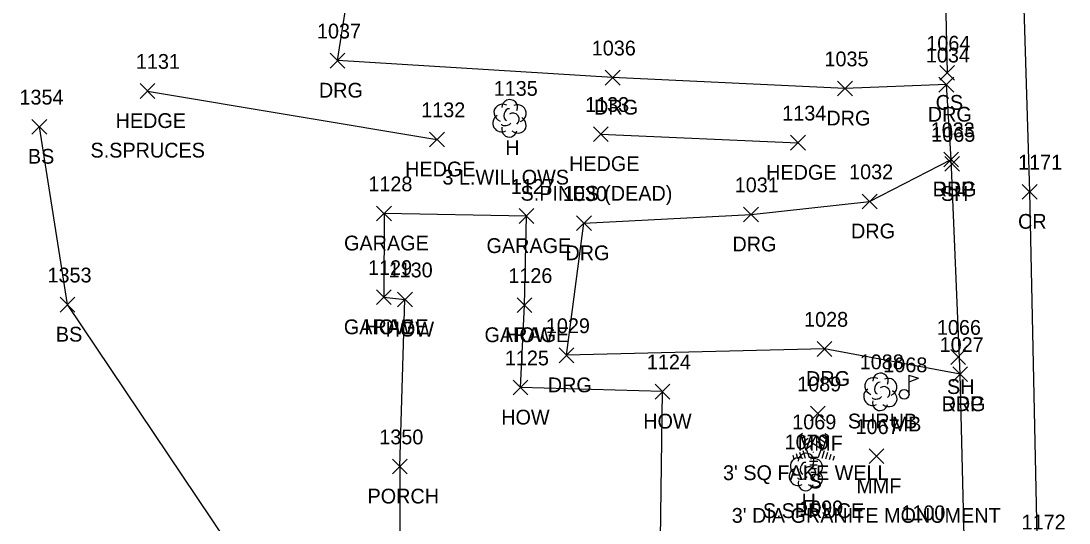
# Model space of a CAD drawing. Extents: x 1609623 to 1616187, y 756677 to 762826.
# Drawn here: x 1610487.5 to 1610629.1, y 761449.2 to 761517.1 of the extents above; entities that cross this region are included whole.
import ezdxf

# ---------------------------------------------------------------- set-up
doc = ezdxf.new("R2010")
doc.units = 0
for name, color, linetype in [('L_A', 7, 'Continuous'), ('L_C', 7, 'Continuous'), ('L_I', 7, 'Continuous'), ('L_TIC', 7, 'Continuous'), ('LAHR', 7, 'Continuous'), ('LBC', 7, 'Continuous'), ('LBF', 7, 'Continuous'), ('LELB', 7, 'Continuous'), ('LMB', 7, 'Continuous'), ('LSH', 7, 'Continuous'), ('LTC', 7, 'Continuous'), ('LTD', 7, 'Continuous'), ('P_A', 7, 'Continuous'), ('P_I', 7, 'Continuous'), ('P_TIC', 7, 'Continuous'), ('PET', 7, 'Continuous'), ('PRC', 7, 'Continuous'), ('R_A', 7, 'Continuous'), ('R_I', 7, 'Continuous'), ('R_TIC', 7, 'Continuous'), ('RDG', 7, 'Continuous')]:
    doc.layers.add(name, color=color, linetype=linetype)

msp = doc.modelspace()

# ---------------------------------------------------------------- linework, layer by layer
at = {"layer": 'L_TIC'}
for points in [[(1610611.63, 761509.1), (1610613.63, 761511.1)], [(1610613.63, 761509.1), (1610611.63, 761511.1)], [(1610503.6, 761506.64), (1610505.6, 761508.64)], [(1610505.6, 761506.64), (1610503.6, 761508.64)], [(1610489, 761501.81), (1610491, 761503.81)], [(1610491, 761501.81), (1610489, 761503.81)], [(1610564.85, 761500.81), (1610566.85, 761502.81)], [(1610566.85, 761500.81), (1610564.85, 761502.81)], [(1610542.71, 761500.09), (1610544.71, 761502.09)], [(1610544.71, 761500.09), (1610542.71, 761502.09)], [(1610591.47, 761499.65), (1610593.47, 761501.65)], [(1610593.47, 761499.65), (1610591.47, 761501.65)], [(1610612.3, 761496.78), (1610614.3, 761498.78)], [(1610614.3, 761496.78), (1610612.3, 761498.78)], [(1610535.56, 761490.08), (1610537.56, 761492.08)], [(1610537.56, 761490.08), (1610535.56, 761492.08)], [(1610554.81, 761489.73), (1610556.81, 761491.73)], [(1610556.81, 761489.73), (1610554.81, 761491.73)], [(1610492.79, 761477.75), (1610494.79, 761479.75)], [(1610494.79, 761477.75), (1610492.79, 761479.75)], [(1610535.53, 761478.75), (1610537.53, 761480.75)], [(1610537.53, 761478.75), (1610535.53, 761480.75)], [(1610535.53, 761478.75), (1610537.53, 761480.75)], [(1610537.53, 761478.75), (1610535.53, 761480.75)], [(1610538.39, 761478.44), (1610540.39, 761480.44)], [(1610540.39, 761478.44), (1610538.39, 761480.44)], [(1610554.53, 761477.68), (1610556.53, 761479.68)], [(1610556.53, 761477.68), (1610554.53, 761479.68)], [(1610554.53, 761477.68), (1610556.53, 761479.68)], [(1610556.53, 761477.68), (1610554.53, 761479.68)], [(1610613.11, 761470.67), (1610615.11, 761472.67)], [(1610615.11, 761470.67), (1610613.11, 761472.67)], [(1610554, 761466.54), (1610556, 761468.54)], [(1610556, 761466.54), (1610554, 761468.54)], [(1610573.18, 761465.99), (1610575.18, 761467.99)], [(1610575.18, 761465.99), (1610573.18, 761467.99)], [(1610594.15, 761463.02), (1610596.15, 761465.02)], [(1610596.15, 761463.02), (1610594.15, 761465.02)], [(1610602.07, 761457.25), (1610604.07, 761459.25)], [(1610604.07, 761457.25), (1610602.07, 761459.25)], [(1610537.7, 761455.86), (1610539.7, 761457.86)], [(1610539.7, 761455.86), (1610537.7, 761457.86)]]:
    msp.add_lwpolyline(points, dxfattribs=at)
at = {"layer": 'LAHR'}
for points in [[(1610504.6, 761507.64), (1610543.71, 761501.09)], [(1610565.85, 761501.81), (1610592.47, 761500.65)]]:
    msp.add_lwpolyline(points, dxfattribs=at)
at = {"layer": 'LBC'}
for points in [[(1610555.53, 761478.68), (1610555.81, 761490.73), (1610536.56, 761491.08), (1610536.53, 761479.75)], [(1610536.53, 761479.75), (1610539.39, 761479.44)], [(1610544.98, 761440.64), (1610573.82, 761440.42), (1610574.18, 761466.99), (1610555, 761467.54), (1610555.53, 761478.68)]]:
    msp.add_lwpolyline(points, dxfattribs=at)
at = {"layer": 'LBF'}
for points in [[(1610538.7, 761456.86), (1610539.39, 761479.44)], [(1610538.7, 761456.86), (1610538.69, 761440.44)]]:
    msp.add_lwpolyline(points, dxfattribs=at)
at = {"layer": 'LELB'}
for points in [[(1610611.15, 761569.53), (1610611.94, 761540.19), (1610612.63, 761510.1)], [(1610528.82, 761426.55), (1610493.79, 761478.75), (1610490, 761502.81)]]:
    msp.add_lwpolyline(points, dxfattribs=at)
at = {"layer": 'LMB'}
for p, q in [((1610607.47, 761469.21), (1610608.77, 761468.83)), ((1610607.48, 761466.62), (1610607.48, 761469.21)), ((1610607.48, 761468.31), (1610608.76, 761468.82)), ((1610606.82, 761466.61), (1610606.82, 761466.61))]:
    msp.add_line(p, q, dxfattribs=at)
msp.add_circle((1610606.82, 761466.61), 0.656, dxfattribs=at)
at = {"layer": 'LSH'}
msp.add_line((1610603.58, 761467.01), (1610603.58, 761467.01), dxfattribs=at)
msp.add_line((1610603.58, 761467.01), (1610603.58, 761467.01), dxfattribs=at)
msp.add_arc((1610603.63, 761468.44), 1.05, 335.5272, 180.9563, dxfattribs=at)
for centre, major_axis, ratio, start_param, end_param in [((1610602.79, 761467.67), (1.21, -0.51), 0.895232, 1.570796, 4.712389), ((1610603.37, 761467.46), (-0.208, -0.792), 0.645439, 3.141593, 6.283185), ((1610604.62, 761467.59), (-1.14, -0.48), 0.949671, 1.570796, 4.712389), ((1610602.5, 761466.3), (0.58, -1.04), 0.959034, 3.141593, 6.283185), ((1610604.08, 761466.84), (-0.5, 0.667), 0.989748, 3.141593, 6.283185), ((1610604.58, 761466.17), (-1.09, 0.79), 0.841452, 1.570796, 4.712389), ((1610603.58, 761465.51), (0.26, 1.06), 0.942809, 1.570796, 4.712389), ((1610603.12, 761466.26), (-0.625, -0.083), 0.423636, 0, 3.141593)]:
    msp.add_ellipse(centre, major_axis=major_axis, ratio=ratio, start_param=start_param, end_param=end_param, dxfattribs=at)
at = {"layer": 'LTC'}
for p, q in [((1610592.73, 761461.1), (1610593.08, 761461.36)), ((1610596.12, 761461.34), (1610596.54, 761461.04)), ((1610592.94, 761460.64), (1610593.46, 761461.02)), ((1610593.14, 761460.17), (1610593.85, 761460.68)), ((1610593.35, 761459.7), (1610594.23, 761460.34)), ((1610593.58, 761459.25), (1610594.59, 761459.98)), ((1610594.59, 761459.98), (1610595.59, 761459.26)), ((1610595.01, 761460.3), (1610595.82, 761459.71)), ((1610595.38, 761460.65), (1610596.06, 761460.15)), ((1610595.75, 761460.99), (1610596.3, 761460.59)), ((1610591.76, 761458.38), (1610591.91, 761457.91)), ((1610592.21, 761458.6), (1610592.43, 761457.95)), ((1610592.67, 761458.81), (1610592.94, 761457.98)), ((1610593.12, 761459.03), (1610593.46, 761458.01)), ((1610593.58, 761459.25), (1610593.97, 761458.06)), ((1610595.59, 761459.26), (1610595.2, 761458.06)), ((1610596.03, 761458.99), (1610595.69, 761457.95)), ((1610596.47, 761458.74), (1610596.18, 761457.85)), ((1610596.91, 761458.49), (1610596.68, 761457.76)), ((1610597.36, 761458.24), (1610597.17, 761457.66)), ((1610595.2, 761458.06), (1610593.97, 761458.06)), ((1610595.16, 761457.56), (1610594.01, 761457.56)), ((1610595.07, 761457.06), (1610594.09, 761457.06)), ((1610594.99, 761456.56), (1610594.16, 761456.56)), ((1610594.91, 761456.06), (1610594.23, 761456.06))]:
    msp.add_line(p, q, dxfattribs=at)
at = {"layer": 'LTD'}
for p, q in [((1610553.49, 761503.99), (1610553.49, 761503.99)), ((1610553.49, 761503.99), (1610553.49, 761503.99)), ((1610593.53, 761456.17), (1610593.53, 761456.17)), ((1610593.53, 761456.17), (1610593.53, 761456.17))]:
    msp.add_line(p, q, dxfattribs=at)
for centre in [(1610553.54, 761505.43), (1610593.57, 761457.61)]:
    msp.add_arc(centre, 1.05, 335.5272, 180.9563, dxfattribs=at)
for centre, major_axis, ratio, start_param, end_param in [((1610552.7, 761504.66), (1.21, -0.51), 0.895232, 1.570796, 4.712389), ((1610553.29, 761504.45), (-0.208, -0.792), 0.645439, 3.141593, 6.283185), ((1610554.54, 761504.58), (-1.14, -0.48), 0.949671, 1.570796, 4.712389), ((1610552.41, 761503.28), (0.58, -1.04), 0.959034, 3.141593, 6.283185), ((1610553.99, 761503.83), (-0.5, 0.667), 0.989748, 3.141593, 6.283185), ((1610554.49, 761503.16), (-1.09, 0.79), 0.841452, 1.570796, 4.712389), ((1610553.49, 761502.49), (0.26, 1.06), 0.942809, 1.570796, 4.712389), ((1610553.04, 761503.24), (-0.625, -0.083), 0.423636, 0, 3.141593), ((1610592.73, 761456.84), (1.21, -0.51), 0.895232, 1.570796, 4.712389), ((1610593.32, 761456.63), (-0.208, -0.792), 0.645439, 3.141593, 6.283185), ((1610594.03, 761456.01), (-0.5, 0.667), 0.989748, 3.141593, 6.283185), ((1610594.57, 761456.76), (-1.14, -0.48), 0.949671, 1.570796, 4.712389), ((1610592.44, 761455.47), (0.58, -1.04), 0.959034, 3.141593, 6.283185), ((1610593.07, 761455.42), (-0.625, -0.083), 0.423636, 0, 3.141593), ((1610594.53, 761455.34), (-1.09, 0.79), 0.841452, 1.570796, 4.712389), ((1610593.53, 761454.67), (0.26, 1.06), 0.942809, 1.570796, 4.712389)]:
    msp.add_ellipse(centre, major_axis=major_axis, ratio=ratio, start_param=start_param, end_param=end_param, dxfattribs=at)
at = {"layer": 'P_TIC'}
for points in [[(1610612.18, 761497.39), (1610614.18, 761499.39)], [(1610614.18, 761497.39), (1610612.18, 761499.39)], [(1610622.77, 761493.01), (1610624.77, 761495.01)], [(1610624.77, 761493.01), (1610622.77, 761495.01)], [(1610613.38, 761468.34), (1610615.38, 761470.34)], [(1610615.38, 761468.34), (1610613.38, 761470.34)]]:
    msp.add_lwpolyline(points, dxfattribs=at)
at = {"layer": 'PET'}
msp.add_lwpolyline([(1610623.62, 761216.53), (1610618.72, 761291.92), (1610617.26, 761347.82), (1610616.06, 761400.59), (1610615, 761443.71), (1610614.38, 761469.34), (1610613.18, 761498.39)], dxfattribs=at)
at = {"layer": 'PRC'}
msp.add_lwpolyline([(1610615.34, 761821.26), (1610616.76, 761769.94), (1610617.49, 761726.01), (1610618.27, 761675.99), (1610618.81, 761645.85), (1610620.71, 761596.25), (1610622.2, 761543.73), (1610623.77, 761494.01), (1610624.8, 761445.35), (1610626.12, 761399.37), (1610627.46, 761348.43), (1610629.43, 761292.43), (1610633.7, 761219.48)], dxfattribs=at)
at = {"layer": 'R_TIC'}
for points in [[(1610529.27, 761510.75), (1610531.27, 761512.75)], [(1610531.27, 761510.75), (1610529.27, 761512.75)], [(1610566.44, 761508.45), (1610568.44, 761510.45)], [(1610568.44, 761508.45), (1610566.44, 761510.45)], [(1610611.52, 761507.5), (1610613.52, 761509.5)], [(1610613.52, 761507.5), (1610611.52, 761509.5)], [(1610597.82, 761506.98), (1610599.82, 761508.98)], [(1610599.82, 761506.98), (1610597.82, 761508.98)], [(1610612.18, 761497.39), (1610614.18, 761499.39)], [(1610614.18, 761497.39), (1610612.18, 761499.39)], [(1610601.15, 761491.71), (1610603.15, 761493.71)], [(1610603.15, 761491.71), (1610601.15, 761493.71)], [(1610585.13, 761489.95), (1610587.13, 761491.95)], [(1610587.13, 761489.95), (1610585.13, 761491.95)], [(1610562.57, 761488.76), (1610564.57, 761490.76)], [(1610564.57, 761488.76), (1610562.57, 761490.76)], [(1610560.2, 761470.9), (1610562.2, 761472.9)], [(1610562.2, 761470.9), (1610560.2, 761472.9)], [(1610595.07, 761471.76), (1610597.07, 761473.76)], [(1610597.07, 761471.76), (1610595.07, 761473.76)], [(1610613.38, 761468.34), (1610615.38, 761470.34)], [(1610615.38, 761468.34), (1610613.38, 761470.34)]]:
    msp.add_lwpolyline(points, dxfattribs=at)
at = {"layer": 'RDG'}
msp.add_lwpolyline([(1610614.38, 761469.34), (1610596.07, 761472.76), (1610561.2, 761471.9), (1610563.57, 761489.76), (1610586.13, 761490.95), (1610602.15, 761492.71), (1610613.18, 761498.39), (1610612.52, 761508.5), (1610598.82, 761507.98), (1610567.44, 761509.45), (1610530.27, 761511.75), (1610533.8, 761534.13), (1610564.49, 761530.77), (1610567.28, 761546.97), (1610568.96, 761568.06), (1610591.55, 761566.46), (1610604.95, 761570.12), (1610610.95, 761577.61), (1610610.75, 761602.13), (1610608.94, 761635.11), (1610595.07, 761652.1), (1610578.79, 761660.9)], dxfattribs=at)

# ---------------------------------------------------------------- texts
at = {"layer": 'L_A'}
for s, p in [('CS', (1610611.07, 761505.1)), ('HEDGE', (1610500.3, 761502.64)), ('H', (1610552.93, 761498.99)), ('BS', (1610488.45, 761497.81)), ('HEDGE', (1610539.41, 761496.09)), ('HEDGE', (1610561.55, 761496.81)), ('HEDGE', (1610588.17, 761495.65)), ('SH', (1610611.78, 761492.78)), ('GARAGE', (1610531.16, 761486.08)), ('GARAGE', (1610550.4, 761485.73)), ('GARAGE', (1610531.13, 761474.75)), ('HOW', (1610533.92, 761474.75)), ('BS', (1610492.23, 761473.75)), ('HOW', (1610536.78, 761474.44)), ('GARAGE', (1610550.13, 761473.68)), ('HOW', (1610552.92, 761473.68)), ('SH', (1610612.6, 761466.67)), ('HOW', (1610552.39, 761462.54)), ('HOW', (1610571.57, 761461.99)), ('SHRUB', (1610599.21, 761462.01)), ('MB', (1610605.13, 761461.61)), ('MMF', (1610592.44, 761459.02)), ('S', (1610593.92, 761453.89)), ('MMF', (1610600.35, 761453.25)), ('PORCH', (1610534.33, 761451.86)), ('H', (1610592.96, 761451.17))]:
    msp.add_text(s, height=2, dxfattribs=at).set_placement(p)
at = {"layer": 'L_C'}
for s, p in [('S.SPRUCES', (1610496.91, 761498.64)), ('3 L.WILLOWS', (1610544.45, 761494.99)), ('S.PINES (DEAD)', (1610555, 761492.81)), ("3' SQ FAKE WELL", (1610582.35, 761455.02)), ("3' DIA GRANITE MONUMENT", (1610583.53, 761449.25)), ('S.SPRUCE', (1610587.74, 761449.89))]:
    msp.add_text(s, height=2, dxfattribs=at).set_placement(p)
at = {"layer": 'L_I'}
for s, p in [('1064', (1610609.81, 761513.1)), ('1131', (1610503.04, 761510.64)), ('1354', (1610487.31, 761505.81)), ('1135', (1610551.37, 761506.99)), ('1133', (1610563.72, 761504.81)), ('1132', (1610541.58, 761504.09)), ('1134', (1610590.35, 761503.65)), ('1065', (1610610.48, 761500.78)), ('1128', (1610534.44, 761494.08)), ('1127', (1610553.68, 761493.73)), ('1353', (1610491.1, 761481.75)), ('1129', (1610534.4, 761482.75)), ('1129', (1610534.4, 761482.75)), ('1130', (1610537.18, 761482.44)), ('1126', (1610553.35, 761481.68)), ('1126', (1610553.35, 761481.68)), ('1066', (1610611.24, 761474.67)), ('1125', (1610552.88, 761470.54)), ('1124', (1610572.06, 761469.99)), ('1088', (1610600.81, 761470.01)), ('1068', (1610604, 761469.61)), ('1089', (1610592.37, 761467.02)), ('1069', (1610591.7, 761461.89)), ('1067', (1610600.25, 761461.25)), ('1350', (1610535.92, 761459.86)), ('1070', (1610590.67, 761459.17)), ('1099', (1610592.63, 761450.25)), ('1099', (1610592.63, 761450.25)), ('1100', (1610606.43, 761449.6))]:
    msp.add_text(s, height=2, dxfattribs=at).set_placement(p)
at = {"layer": 'LTC'}
msp.add_text('.', height=1.04, rotation=270, dxfattribs=at).set_placement((1610594.47, 761459))
at = {"layer": 'P_A'}
for s, p in [('RDP', (1610610.66, 761493.39)), ('CR', (1610622.2, 761489.01)), ('RDP', (1610611.87, 761464.34))]:
    msp.add_text(s, height=2, dxfattribs=at).set_placement(p)
at = {"layer": 'P_I'}
for s, p in [('1033', (1610610.4, 761501.39)), ('1171', (1610622.21, 761497.01)), ('1027', (1610611.61, 761472.34)), ('1172', (1610622.68, 761448.35))]:
    msp.add_text(s, height=2, dxfattribs=at).set_placement(p)
at = {"layer": 'R_A'}
for p in [(1610527.76, 761506.75), (1610564.93, 761504.45), (1610596.31, 761502.98), (1610610.01, 761503.5), (1610610.66, 761493.39), (1610599.64, 761487.71), (1610583.62, 761485.95), (1610561.06, 761484.76), (1610593.56, 761467.76), (1610558.68, 761466.9), (1610611.87, 761464.34)]:
    msp.add_text('DRG', height=2, dxfattribs=at).set_placement(p)
at = {"layer": 'R_I'}
for s, p in [('1037', (1610527.5, 761514.75)), ('1036', (1610564.62, 761512.45)), ('1034', (1610609.75, 761511.5)), ('1035', (1610596.05, 761510.98)), ('1033', (1610610.4, 761501.39)), ('1032', (1610599.38, 761495.71)), ('1031', (1610583.93, 761493.95)), ('1030', (1610560.72, 761492.76)), ('1029', (1610558.42, 761474.9)), ('1028', (1610593.3, 761475.76)), ('1027', (1610611.61, 761472.34))]:
    msp.add_text(s, height=2, dxfattribs=at).set_placement(p)

doc.saveas('drawing.dxf')
